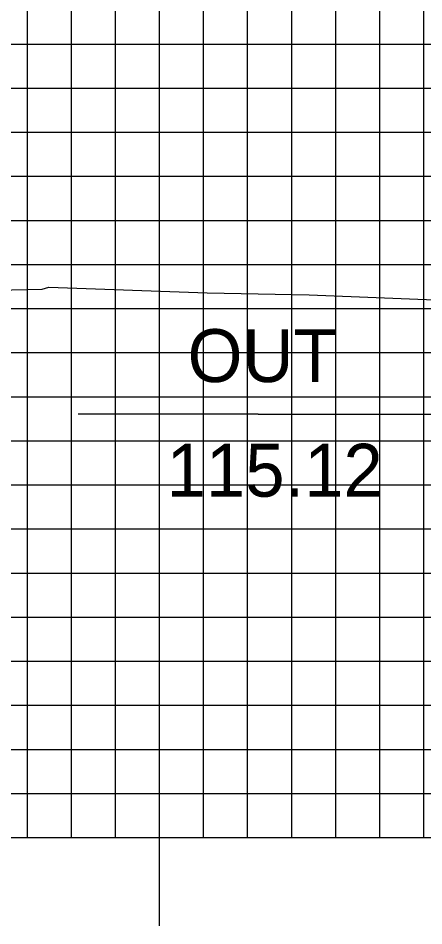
# Model space of a CAD drawing. Extents: x 853328 to 853671, y 364661 to 364881.
# Drawn here: x 853440.08 to 853449.3, y 364684.37 to 364704.96 of the extents above; entities that cross this region are included whole.
import ezdxf

# ---------------------------------------------------------------- set-up
doc = ezdxf.new("R2010")
doc.units = 0
for name, color, linetype in [('ANNOTATION', 7, 'Continuous'), ('MAJOR', 7, 'Continuous'), ('MINOR', 7, 'Continuous'), ('S_Roadway_Centerline', 7, 'Continuous')]:
    doc.layers.add(name, color=color, linetype=linetype)

msp = doc.modelspace()

# ---------------------------------------------------------------- linework, layer by layer
at = {"layer": 'ANNOTATION'}
msp.add_line((853445.534, 364695.98), (853441.444, 364695.98), dxfattribs=at)
msp.add_lwpolyline([(853445.534, 364695.98), (853451.226, 364695.98), (853453.863, 364691.493)], dxfattribs=at)
at = {"layer": 'MAJOR'}
for p, q in [((853443.294, 364686.374), (853443.294, 364721.374)), ((853353.294, 364701.374), (853633.294, 364701.374)), ((853353.294, 364696.374), (853633.294, 364696.374)), ((853353.294, 364691.374), (853633.294, 364691.374)), ((853353.294, 364686.374), (853633.294, 364686.374)), ((853353.294, 364686.374), (853633.294, 364686.374)), ((853443.294, 364684.37), (853443.294, 364686.374))]:
    msp.add_line(p, q, dxfattribs=at)
at = {"layer": 'MINOR'}
for p, q in [((853440.294, 364686.374), (853440.294, 364721.374)), ((853441.294, 364686.374), (853441.294, 364721.374)), ((853442.294, 364686.374), (853442.294, 364721.374)), ((853444.294, 364686.374), (853444.294, 364721.374)), ((853445.294, 364686.374), (853445.294, 364721.374)), ((853446.294, 364686.374), (853446.294, 364721.374)), ((853447.294, 364686.374), (853447.294, 364721.374)), ((853448.294, 364686.374), (853448.294, 364721.374)), ((853449.294, 364686.374), (853449.294, 364721.374)), ((853353.294, 364704.374), (853633.294, 364704.374)), ((853353.294, 364703.374), (853633.294, 364703.374)), ((853353.294, 364702.374), (853633.294, 364702.374)), ((853353.294, 364700.374), (853633.294, 364700.374)), ((853353.294, 364699.374), (853633.294, 364699.374)), ((853353.294, 364698.374), (853633.294, 364698.374)), ((853353.294, 364697.374), (853633.294, 364697.374)), ((853353.294, 364695.374), (853633.294, 364695.374)), ((853353.294, 364694.374), (853633.294, 364694.374)), ((853353.294, 364693.374), (853633.294, 364693.374)), ((853353.294, 364692.374), (853633.294, 364692.374)), ((853353.294, 364690.374), (853633.294, 364690.374)), ((853353.294, 364689.374), (853633.294, 364689.374)), ((853353.294, 364688.374), (853633.294, 364688.374)), ((853353.294, 364687.374), (853633.294, 364687.374))]:
    msp.add_line(p, q, dxfattribs=at)
at = {"layer": 'S_Roadway_Centerline'}
msp.add_lwpolyline([(853436.474, 364698.724), (853440.63, 364698.815), (853440.781, 364698.863), (853444.377, 364698.733), (853446.689, 364698.689), (853453.345, 364698.418), (853461.566, 364698.035), (853463.658, 364697.947), (853466.152, 364698.291), (853473.152, 364699.194), (853477.467, 364699.114), (853483.807, 364699.043)], dxfattribs=at)

# ---------------------------------------------------------------- texts
at = {"layer": 'ANNOTATION'}
for s, p in [('OUT', (853443.93, 364696.706)), ('115.12', (853443.455, 364694.106))]:
    msp.add_text(s, height=1.2, dxfattribs=at).set_placement(p)

doc.saveas('drawing.dxf')
